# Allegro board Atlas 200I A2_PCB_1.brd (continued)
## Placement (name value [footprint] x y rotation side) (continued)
R361  2.2  [SR0402-TB]  90.31 16.03 270 top
R362  75  [SR0805-TB]  3.35 23.7 270 top
R363  75  [SR0805-TB]  7.39 21.28 270 top
R364  2.2  [SR0402-TB]  87 16.03 270 top
R365  200  [SR0402-TA]  33.96 26.67 0 top
R366  200  [SR0402-TA]  33.96 22.61 0 top
R367  200  [SR0402-TA]  33.96 25.65 0 top
R368  200  [SR0402-TA]  33.96 23.62 0 top
R369  10k*  [SR0402-TA]  105.41 42.32 180 top
R370  0  [SR0402-TA]  108.95 37.19 270 top
R371  47k  [SR0402-TA]  99.26 41.66 90 top
R372  2.2  [SR0805-TB]  115.24 21.7 180 top
R373  2.2  [SR0805-TB]  115.24 19.99 180 top
R374  10k  [SR0402-TA]  108.46 41.55 270 top
R375  0*  [SR0402-TA]  109.09 38.68 0 top
R376  10k*  [SR0402-TA]  106.74 37.19 90 top
R377  10k  [SR0402-TA]  97.23 41.66 270 top
R378  15k  [SR0402-TA]  98.3 39.21 0 top
R379  0  [SR0402-TA]  97.03 39.59 270 top
R380  33  [SR0402-TA]  108.46 39.92 90 top
R381  33  [SR0402-TA]  102.18 29.01 90 top
R382  3m  [SR2512B-TF]  108.58 21.39 180 top
R383  2.2*  [SR0402-TB]  113.49 24.08 0 top
R384  33  [SR0402-TA]  80.03 19.43 270 top
R385  10k  [SR0402-TA]  81.07 21.26 270 top
R386  4.7k  [SR0402-TA]  82.88 21.26 270 top
R387  10k  [SR0402-TA]  84.75 19.43 90 top
R388  47k  [SR0402-TA]  86.62 19.43 270 top
R389  2.2  [SR0805-TB]  84.76 29.34 270 top
R390  47K  [SR0402-TA]  82.35 27.21 180 top
R391  33  [SR0402-TA]  78.23 21.21 270 top
R392  5.1k  [SR0402-TA]  77.22 21.21 90 top
R393  27k  [SR0402-TA]  76.51 23.14 270 top
R394  47k  [SR0402-TA]  74.58 23.14 90 top
R395  475  [SR0402-TA]  77.83 18.61 180 top
R396  0  [SR0402-TA]  89.24 38.74 270 top
R397  2.2  [SR0402-TB]  87.91 16.03 270 top
R398  1k*  [SR0402-TA]  91.15 37.29 90 top
R399  2.49k  [SR0402-TA]  87.47 38.74 90 top
R400  1k*  [SR0402-TA]  53.49 63.25 180 top
R401  2k  [SR0402-TA]  88.55 32.38 0 top
R402  2k  [SR0402-TA]  86.62 38.74 90 top
R403  200  [SR0402-TA]  82.02 19.43 270 top
R404  2k  [SR0402-TA]  81.98 21.26 90 top
R405  1k*  [SR0402-TA]  53.49 67.26 180 top
R406  475  [SR0402-TA]  75.72 19.63 180 top
R407  1k  [SR0402-TA]  77.83 19.63 0 top
R408  100*  [SR0402-TA]  94.92 26.16 90 top
R409  100*  [SR0402-TA]  67.05 26.26 180 top
R410  330  [SR0402-TA]  73.43 42.85 270 top
R411  330  [SR0402-TA]  80.67 43.74 270 top
R412  1k  [SR0402-TA]  75.08 41.71 270 top
R413  1k  [SR0402-TA]  68.58 41.66 270 top
R414  1k  [SR0402-TA]  68.58 39.88 270 top
R415  1k  [SR0402-TA]  75.59 43.1 0 top
R416  0  [SR0402-TA]  24.82 79.78 90 top
R417  330  [SR0402-TA]  100.71 17.42 270 top
R418  330  [SR0402-TA]  87.91 42.85 270 top
R419  330  [SR0402-TA]  95.15 42.72 270 top
R420  1k  [SR0402-TA]  89.69 40.69 270 top
R421  1k  [SR0402-TA]  82.32 40.69 90 top
R422  1k  [SR0402-TA]  82.83 42.09 0 top
R423  1k  [SR0402-TA]  90.07 42.09 0 top
R424  0  [SR0402-TA]  25.83 79.78 90 top
R425  33  [SR0402-TA]  8 73.03 180 top
R426  33  [SR0402-TA]  2.41 75.91 90 top
R427  33  [SR0402-TA]  3.43 75.91 90 top
R428  33  [SR0402-TA]  8 72.01 180 top
R429  0  [SR0402-TA]  88.04 80.26 180 top
R430  0*  [SR0402-TA]  87.22 80.26 0 top
R431  0  [SR0402-TA]  88.04 78.92 180 top
R432  0*  [SR0402-TA]  87.22 78.92 0 top
R433  33  [SR0402-TA]  124.09 70.1 0 top
R434  0  [SR0402-TA]  95.06 71.25 270 top
R435  33  [SR0402-TA]  124.09 76.38 0 top
R436  33  [SR0402-TA]  124.09 87.17 0 top
R437  33  [SR0402-TA]  124.09 83.05 0 top
R438  33  [SR0402-TA]  124.09 81.99 0 top
R439  33  [SR0402-TA]  124.09 79.94 0 top
R440  33  [SR0402-TA]  124.09 80.96 0 top
R441  0*  [SR0402-TA]  95.06 70.43 90 top
R442  33  [SR0402-TA]  124.09 90.04 0 top
R443  33  [SR0402-TA]  123.89 101.6 0 top
R444  33  [SR0402-TA]  124.09 69.12 180 top
R445  33  [SR0402-TA]  124.09 70.95 180 top
R446  0  [SR0402-TA]  96.39 71.25 270 top
R447  33  [SR0402-TA]  123.99 74.52 180 top
R448  33  [SR0402-TA]  124.09 78.96 180 top
R449  33  [SR0402-TA]  124.09 84.08 180 top
R450  33  [SR0402-TA]  124.09 86.14 180 top
R451  0*  [SR0402-TA]  96.39 70.43 90 top
R452  33  [SR0402-TA]  123.89 104.65 180 top
R453  33  [SR0402-TA]  123.89 102.62 180 top
R454  33  [SR0402-TA]  124.09 71.81 0 top
R455  33  [SR0402-TA]  123.89 105.66 0 top
R456  33  [SR0402-TA]  123.89 106.68 0 top
R457  1k  [SR0402-TA]  21.7 73.11 180 top
R458  33  [SR0402-TA]  105.66 84.07 180 top
R459  6.2k  [SR0402-TA]  90.04 74.04 90 top
R460  10k  [SR0402-TA]  88.16 70.76 90 top
R461  200  [SR0402-TA]  127.47 32.38 0 top
R462  10k  [SR0402-TA]  129.92 32.44 180 top
R463  200  [SR0402-TA]  129.92 21.26 0 top
R464  10k  [SR0402-TA]  127.47 21.26 180 top
R465  200  [SR0402-TA]  127.47 26.85 0 top
R466  10k  [SR0402-TA]  129.92 26.85 180 top
R467  10k  [SR0402-TA]  88.52 74.3 0 top
R468  0*  [SR0402-TA]  92.46 87.6 270 top
R469  33  [SR0402-TA]  132.84 43.05 0 top
R470  33  [SR0402-TA]  130.94 43.05 0 top
R471  33  [SR0402-TA]  129.16 43.05 0 top
R472  33  [SR0402-TA]  127.25 43.05 0 top
R473  0  [SR0402-TA]  92.46 86.79 90 top
R474  0*  [SR0402-TA]  91.12 87.6 270 top
R475  0  [SR0402-TA]  91.12 86.79 90 top
R476  0  [SR0402-TA]  88.04 77.84 180 top
R477  0*  [SR0402-TA]  87.22 77.84 0 top
R478  10k  [SR0402-TA]  104.6 45.39 0 top
R479  10k  [SR0402-TA]  105.94 43.84 90 top
R480  10k  [SR0402-TA]  104.6 44.37 0 top
R481  33  [SR0402-TA]  113.14 103.38 180 top
R482  33  [SR0402-TA]  113.14 102.36 180 top
R483  4.7k*  [SR0402-TA]  121.44 102.36 180 top
R484  4.7k*  [SR0402-TA]  121.44 103.38 180 top
R485  4.7k*  [SR0402-TA]  121.44 101.35 180 top
R486  4.7k  [SR0402-TA]  119.28 102.36 0 top
R487  4.7k  [SR0402-TA]  119.28 101.35 0 top
R488  4.7k  [SR0402-TA]  119.28 103.38 0 top
R489  4.7k  [SR0402-TA]  99.06 116.33 180 top
R490  33  [SR0402-TA]  87.76 116.85 0 top
R491  33  [SR0402-TA]  87.76 115.96 0 top
R492  33  [SR0402-TA]  96.81 116.35 0 top
R493  33  [SR0402-TA]  96.81 117.36 0 top
R494  4.7k  [SR0402-TA]  99.09 118.38 0 top
R495  4.7k  [SR0402-TA]  99.09 117.36 0 top
R496  4.7k  [SR0402-TA]  87.76 117.71 180 top
R497  4.7k  [SR0402-TA]  87.76 115.09 180 top
R498  33  [SR0402-TA]  117.55 100.56 0 top
R499  33  [SR0402-TA]  115.72 100.56 180 top
R500  4.7k*  [SR0402-TA]  124.03 100.3 0 top
R501  4.7k  [SR0402-TA]  124.03 99.29 0 top
R502  4.7k*  [SR0402-TA]  124.03 98.27 0 top
R503  4.7k*  [SR0402-TA]  124.03 97.26 0 top
R504  4.7k*  [SR0402-TA]  124.03 96.24 0 top
R505  4.7k  [SR0402-TA]  124.03 95.22 0 top
R506  4.7k*  [SR0402-TA]  124.03 94.21 0 top
R507  4.7k  [SR0402-TA]  124.03 93.19 0 top
R508  4.7k*  [SR0402-TA]  108.86 101.22 180 top
R509  4.7k*  [SR0402-TA]  108.86 100.2 180 top
R510  4.7k*  [SR0402-TA]  108.86 99.19 180 top
R511  4.7k  [SR0402-TA]  108.86 98.17 180 top
R512  4.7k*  [SR0402-TA]  108.86 97.16 180 top
R513  4.7k*  [SR0402-TA]  108.86 96.14 180 top
R514  4.7k*  [SR0402-TA]  108.86 95.12 180 top
R515  4.7k*  [SR0402-TA]  108.86 94.11 180 top
R516  1k  [SR0402-TA]  121.94 100.3 180 top
R517  1k*  [SR0402-TA]  121.94 99.29 180 top
R518  1k  [SR0402-TA]  121.94 98.27 180 top
R519  1k  [SR0402-TA]  121.94 97.26 180 top
R520  1k  [SR0402-TA]  121.94 96.24 180 top
R521  1k*  [SR0402-TA]  121.94 95.22 180 top
R522  1k  [SR0402-TA]  121.94 94.21 180 top
R523  1k*  [SR0402-TA]  121.94 93.19 180 top
R524  1k  [SR0402-TA]  110.95 101.22 0 top
R525  1k  [SR0402-TA]  110.95 100.2 0 top
R526  1k  [SR0402-TA]  110.95 99.19 0 top
R527  1k*  [SR0402-TA]  110.95 98.17 0 top
R528  1k  [SR0402-TA]  110.95 97.16 0 top
R529  1k  [SR0402-TA]  110.95 96.14 0 top
R530  1k  [SR0402-TA]  110.95 95.12 0 top
R531  1k  [SR0402-TA]  110.95 94.11 0 top
R532  4.7k*  [SR0402-TA]  108.86 93.09 180 top
R533  4.7k*  [SR0402-TA]  124.03 91.16 0 top
R534  4.7k*  [SR0402-TA]  124.03 92.18 0 top
R535  1k  [SR0402-TA]  121.94 92.18 180 top
R536  1k  [SR0402-TA]  121.94 91.16 180 top
R537  1k  [SR0402-TA]  110.95 93.09 0 top
R538  0  [SR0402-TA]  88.04 76.51 180 top
R539  0*  [SR0402-TA]  87.22 76.51 0 top
R540  0  [SR0402-TA]  90.1 71.25 270 top
R541  0*  [SR0402-TA]  90.1 70.43 90 top
R542  0  [SR0402-TA]  91.44 71.25 270 top
R543  0*  [SR0402-TA]  91.44 70.43 90 top
R544  0  [SR0402-TA]  86.45 70.76 270 top
R545  0*  [SR0402-TA]  86.86 69.22 180 top
R546  10k  [SR0402-TA]  87.31 70.76 90 top
R547  4.7k*  [SR0402-TA]  73.53 92.71 270 top
R548  1k  [SR0402-TA]  75.31 91.19 180 top
R549  0  [SR0402-TA]  75.51 96.37 0 top
R550  33  [SR0402-TA]  102.23 85.28 180 top
R551  4.7k*  [SR0402-TA]  105.66 85.09 180 top
R552  4.7k  [SR0402-TA]  124.09 88.03 0 top
R553  4.7k  [SR0402-TA]  121.55 79.22 180 top
R554  1k  [SR0402-TA]  107.44 85.09 180 top
R555  0  [SR0402-TA]  105.66 88.65 180 top
R556  33  [SR0402-TA]  122.13 80.92 90 top
R557  33  [SR0402-TA]  119.91 80.92 90 top
R558  0  [SR0402-TA]  65.43 91.9 90 top
R559  0  [SR0402-TA]  66.45 91.9 90 top
R560  1M*  [SR0402-TA]  65.94 93.29 0 top
R561  33*  [SR0402-TA]  16.76 117.35 180 top
R562  33*  [SR0402-TA]  28.45 117.22 180 top
R563  33*  [SR0402-TA]  28.45 116.2 0 top
R564  4.7k  [SR0402-TA]  71.21 76.28 90 top
R565  4.7k  [SR0402-TA]  97.58 60.44 0 top
R566  4.7k  [SR0402-TA]  110.26 76.32 0 top
R567  33*  [SR0402-TA]  16.76 118.36 0 top
R568  4.7k  [SR0402-TA]  72.92 72.03 270 top
R569  4.7k  [SR0402-TA]  70.35 72.03 90 top
R570  6.04k*  [SR0402-TA]  83.47 92.2 270 top
R571  4.7k  [SR0402-TA]  97.58 61.5 0 top
R572  33  [SR0402-TA]  121.02 80.92 90 top
R573  4.7k*  [SR0402-TA]  91.03 104.9 270 top
R574  0*  [SR0402-TA]  82.61 92.2 90 top
R575  33  [SR0402-TA]  120.81 57.71 90 top
R576  10k*  [SR0402-TA]  80.52 105.79 180 top
R577  1M*  [SR0402-TA]  80.52 104.78 180 top
R578  1M*  [SR0402-TA]  81.28 91.9 180 top
R579  0*  [SR0402-TA]  80.9 93.17 270 top
R580  0*  [SR0402-TA]  81.75 93.17 270 top
R581  0*  [SR0402-TA]  100.19 87.68 90 top
R582  0*  [SR0402-TA]  98.86 87.68 90 top
R583  0*  [SR0402-TA]  102.55 87.68 90 top
R584  0*  [SR0402-TA]  101.21 87.68 90 top
R585  0*  [SR0402-TA]  100.19 88.49 270 top
R586  0*  [SR0402-TA]  98.86 88.49 270 top
R587  0*  [SR0402-TA]  102.55 88.49 270 top
R588  0*  [SR0402-TA]  101.21 88.49 270 top
R589  4.7k  [SR0402-TA]  124.15 64.66 0 top
R590  0  [SR0402-TA]  102.23 83.96 0 top
R591  4.7k  [SR0402-TA]  115.98 67.55 180 top
R592  0  [SR0402-TA]  102.23 82.63 0 top
R593  0*  [SR0402-TA]  103.05 83.96 180 top
R594  4.7k  [SR0402-TA]  87.68 114.13 0 top
R595  33  [SR0402-TA]  96.77 114.05 180 top
R596  33  [SR0402-TA]  96.77 115.06 180 top
R597  0*  [SR0402-TA]  103.05 82.63 180 top
R598  4.7k*  [SR0402-TA]  88.52 104.9 90 top
R599  4.7k  [SR0402-TA]  87.68 112.42 180 top
R600  4.7k  [SR0402-TA]  87.68 113.27 180 top
R601  4.7k  [SR0402-TA]  99.06 114.05 180 top
R602  4.7k  [SR0402-TA]  99.06 115.06 180 top
R603  4.7k  [SR0402-TA]  111.19 115.32 180 top
R604  33  [SR0402-TA]  102.75 116.97 0 top
R605  33  [SR0402-TA]  102.75 115.95 0 top
R606  0*  [SR0402-TA]  93.78 105.92 90 top
R607  10k*  [SR0402-TA]  28.45 118.24 180 top
R608  4.7k  [SR0402-TA]  111.19 117.35 0 top
R609  4.7k  [SR0402-TA]  111.19 116.33 0 top
R610  4.7k  [SR0402-TA]  100.72 116.97 0 top
R611  4.7k  [SR0402-TA]  100.72 115.95 0 top
R612  33  [SR0402-TA]  114.2 69.25 90 top
R613  33  [SR0402-TA]  74.89 84.83 180 top
R614  33  [SR0402-TA]  74.89 78.44 180 top
R615  33  [SR0402-TA]  74.89 77.33 180 top
R616  33  [SR0402-TA]  74.89 83.98 180 top
R617  33  [SR0402-TA]  74.89 83.12 180 top
R618  33  [SR0402-TA]  74.9 79.49 180 top
R619  10k*  [SR0402-TA]  16.76 116.33 0 top
R620  33  [SR0402-TA]  114.21 80.92 90 top
R621  33  [SR0402-TA]  87.22 86.42 180 top
R622  33  [SR0402-TA]  70.35 76.28 270 top
R623  33  [SR0402-TA]  73.77 72.03 90 top
R624  33  [SR0402-TA]  71.21 72.03 270 top
R625  33  [SR0402-TA]  97.58 62.51 180 top
R626  33  [SR0402-TA]  110.11 77.33 180 top
R627  33  [SR0402-TA]  70 80.45 0 top
R628  4.7k  [SR0402-TA]  74.89 80.63 180 top
R629  4.7k  [SR0402-TA]  115.85 79.22 180 top
R630  10k*  [SR0402-TA]  30.61 116.2 0 top
R631  1k*  [SR0402-TA]  30.61 115.19 0 top
R632  0  [SR0402-TA]  91.14 106.65 270 top
R633  1k*  [SR0402-TA]  89.79 104.9 0 top
R634  33  [SR0402-TA]  113.1 80.92 90 top
R635  33  [SR0402-TA]  118.95 57.71 90 top
R636  33  [SR0402-TA]  113.22 57.66 90 top
R637  33  [SR0402-TA]  121.74 57.71 90 top
R638  33  [SR0402-TA]  116.55 57.66 90 top
R639  10k*  [SR0402-TA]  89.79 106.93 0 top
R640  0  [SR0402-TA]  19.94 111.3 180 top
R641  33  [SR0402-TA]  116.42 80.92 90 top
R642  0*  [SR0402-TA]  30.61 118.24 180 top
R643  10k  [SR0402-TA]  81.79 70.36 90 top
R644  0  [SR0402-TA]  80.77 70.36 270 top
R645  0*  [SR0402-TA]  79.76 70.36 270 top
R646  4.7k*  [SR0402-TA]  94.56 101.35 0 top
R647  10k  [SR0402-TA]  47.8 30.07 270 top
R648  10k  [SR0402-TA]  58.93 15.52 270 top
R649  10k  [SR0402-TA]  100.86 79.73 90 top
R650  0  [SR0402-TA]  111.58 112.99 270 top
R651  4.7k*  [SR0402-TA]  88.98 103.64 0 top
R652  4.7k*  [SR0402-TA]  82.82 100.46 270 top
R669  33  [SR0402-TA]  115.44 57.66 90 top
R670  33  [SR0402-TA]  115.31 80.92 90 top
R671  33  [SR0402-TA]  113.09 69.25 90 top
R674  33  [SR0402-TA]  114.33 57.66 90 top
R676  33  [SR0402-TA]  120.11 69.25 90 top
R678  33  [SR0402-TA]  119.25 69.25 90 top
R703  4.7k  [SR0402-TA]  93.09 45.01 90 top
R704  4.7k  [SR0402-TA]  94.11 45.01 90 top
RT1  RT  [SF1913]  68.63 29.49 0 top
RT2  RT  [SF1913]  75.95 4.83 270 top
S1  NONE  [TSW5-TG-A]  129.92 30.02 0 top
S2  NONE  [TSW5-TG-A]  129.92 24.43 0 top
S3  NONE  [TSW5-TG-A]  129.92 18.85 0 top
SW1  NONE  [SDSW8-L-B]  129.04 49.5 180 top
T1  NONE  [SL4-0101F]  110.82 11.71 180 top
T2  NONE  [SL4-0101F]  107.69 11.71 180 top
T3  NONE  [SL4-0101F]  106.29 11.71 180 top
T4  NONE  [SL4-0101F]  109.1 11.71 180 top
T5  -99.999999H*  [SL4-0102]  51.05 25.96 90 top
T6  -99.999999H*  [SL4-0102]  41.38 26.25 180 top
T7  -99.999999H*  [SL4-0102]  36.68 26.25 180 top
T8  -99.999999H*  [SL4-0102]  51.05 23.93 90 top
T9  -99.999999H*  [SL4-0102]  43.84 26.25 180 top
T10  -99.999999H*  [SL4-0102]  38.99 26.25 180 top
T19  NONE  [STFM24-40-280]  8.5 32.45 180 top
T20  NONE  [STFM24-40-280]  24.43 32.45 180 top
T21  -99.999999H  [SL4-0102]  103.3 14.05 180 top
TP8  NONE  [TP2-50-5MIL]  126.17 117.36 90 top
TP9  NONE  [TP2-50-5MIL]  8.79 2.95 270 top
U1  NONE  [MLF48A-040-0606L]  11.75 53.59 0 top
U2  NONE  [MLF48A-040-0606L]  57.91 34.16 0 top
U3  SRV05-4  [SOT23-6A]  20.95 98.3 90 top
U4  SRV05-4  [SOT23-6A]  20.95 103.89 270 top
U5  NONE  [MLF20A-050-0503L]  108.18 14.15 180 top
U6  SRV05-4  [SOT23-6A]  103.29 10.24 90 top
U7  NONE  [SOP8-50-154C]  98.73 26.19 0 top
U8  NONE  [MLF6C-065-0202L]  46.79 32.36 0 top
U9  NONE  [MLF6C-065-0202L]  57.91 17.81 0 top
U10  NONE  [MLF48T-050-0707L]  61.21 115.4 0 top
U11  NONE  [SBAT2-1512]  16 66.8 270 top
U12  NONE  [SOP10-20-118]  102.97 39.78 270 top
U13  NONE  [MLF14A-050-0404L]  83.01 24.46 270 top
U14  NONE  [SOT666-6A]  73.3 18.75 270 top
U15  NONE  [MLF20J-050-0404L]  88.06 35.61 180 top
U16  NONE  [SOT23-5F]  101.02 44.37 90 top
U17  NONE  [MLF8A-050-0203L]  116.23 102.36 90 top
U18  NONE  [SOP8-26-118C]  92.23 117.29 270 top
U19  NONE  [SOP24-26-173A]  116.57 95.66 90 top
U20  NONE  [SOP14-26-173C]  120.38 62.89 0 top
U21  NONE  [SOP14-26-173C]  120.05 74.56 0 top
U22  NONE  [SOP8-26-118C]  92.23 113.56 90 top
U23  NONE  [SOP8-26-118C]  107.02 116.46 270 top
U24  NONE  [SOP14-26-173C]  79.88 78.46 90 top
U25  NONE  [SOP14-26-173C]  79.96 84.38 90 top
U26  NONE  [MLF10P-050-0303L]  113.89 110.45 270 top
U27  *  [BGA153-20-1414-ENIG]  6.31 95.66 90 top
U28  SRV05-4  [SOT23-6A]  61.72 16.94 270 top
U29  SRV05-4  [SOT23-6A]  80.54 15.6 180 top
U30  NONE  [SOT23-8]  126.82 37.34 180 top
U31  SRV05-4  [SOT23-6A]  46.96 24.87 180 top
U32  NONE  [SOP14-26-173C]  114.47 62.89 0 top
U33  NONE  [SOP14-26-173C]  114.35 74.56 0 top
U34  NONE  [SOP14-26-173C]  114.35 86.23 0 top
U35  NONE  [SOP14-26-173C]  120.06 86.23 0 top
U36  NONE  [MLF76L-040-0909L]  95.35 80.22 0 top
U37  *  [SOP8-50-208]  22.62 116.3 90 top
U38  *  [MLF76Q-040-0909L]  88.29 98.17 90 top
VCXO1  100MHz  [HSX4-0503]  79.22 116.41 90 top
X1  25MHz  [HSX4-0302B]  4.57 53.34 270 top
X2  25MHz  [HSX4-0302B]  50.93 32.89 270 top
X3  12MHz  [SX4-0303K]  69.85 92.46 90 top
X4  25MHz*  [HSX4-0302B]  83.82 89.15 180 top

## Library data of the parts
C1-C3 C6 C21 C22 C25 C26 C41 C42 C142 C145 = SC0402: signal model: DEFAULT_CAPACITOR_220000pF_2_1
C4 C5 C7 C8 C23 C24 C27 C28 C30 C31 C254 C255 = SC1206-TF
C9 C10 C14 C15 C17 C18 C34 C37 C49 C50 C52 C53 C72 C75 C88 C113 C115 C118-C120 C127 C129-C134 C136-C141 C143 C144 C146 C147 C152 C157 C158 C161 C162 C164 C168-C173 C176 C185-C188 C193-C196 C214 C238 C243 C260 C262 C276 C277 C283-C287 C290-C292 C294-C296 C298-C301 C303 C304 C308 C310 = SC0402-PB: signal model: DEFAULT_CAPACITOR_100000pF_2_1
C11 C16 C19 C20 C29 C32 C35 C155 C156 C163 C167 C182 C217 C222-C225 C228 C231 C232 C241 C247-C249 C259 C261 C266 C309 C322 = SC0805-TD
C12 C40 C48 C59 C74 C78 C94 C100 C101 C123-C126 C153 C165 C175 C181 C205 C210 C220 C245 C253 C263 C270 C302 C346 C347 C352 C355-C361 C364-C366 C368-C370 = SC0603-TD
C13 C63 C82 C87 C201-C204 C242 C264 C265 C271 C273-C275 C280-C282 = SC0402-PB: signal model: DEFAULT_CAPACITOR_10000pF_2_1
C33 C36 C38 C39 C43 C58 C60 C61 C67 C71 C76 C79 C80 C83 C84 C89 C91-C93 C96-C99 C102-C108 C110-C112 C114 C180 C206-C209 C213 C227 C246 C251 C252 C256 C269 C272 C278 C279 C297 C305 C311 C313 C318 C323-C342 C345 C348-C351 C353 C354 C362 C363 C371-C376 = SC0402-PB
C44 C65 C86 C109 C121 C122 C128 C135 C150 C151 C154 C159 C160 C166 C174 C178 C221 C239 C250 C306 C307 C312 C314 C317 C343 C344 = SC0402-PA
C45 C68 = SC0402: signal model: DEFAULT_CAPACITOR_10.000000pF_2_1
C46 C47 C64 = SC0402-PA: signal model: DEFAULT_CAPACITOR_30.000000pF_2_1
C51 C56 C70 C73 C85 C90 C189-C191 C197-C199 C288 C293 = SC0402-PC: signal model: DEFAULT_CAPACITOR_1e+06pF_2_1
C54 C62 C66 C77 C81 C117 C240 = SC0402-PC
C55 C69 C367 = SC0402-PD
C57 = SC0402-PC: signal model: DEFAULT_CAPACITOR_4.7e+06pF_2_1
C95 = SC0402
C116 C184 = SC0402-PA: signal model: DEFAULT_CAPACITOR_33.000000pF_2_1
C148 C149 = SC0402-PA: signal model: DEFAULT_CAPACITOR_150.000000pF_2_1
C177 = SC0402-PA: signal model: DEFAULT_CAPACITOR_100000pF_2_1
C179 = SC0402-PA: signal model: DEFAULT_CAPACITOR_220.000000pF_2_1
C183 C211 C212 C215 C216 C218 C219 C226 C236 C258 C267 C268 = SC0603-TC
C192 C200 = SC1206E
C229 C230 C233 C235 C257 C321 = SC0402-PA: signal model: DEFAULT_CAPACITOR_1000pF_2_1
C234 = SC0402-PA: signal model: DEFAULT_CAPACITOR_15.000000pF_2_1
C237 = SC0402-PB: signal model: DEFAULT_CAPACITOR_2200pF_2_1
C244 = SC0402-PB: signal model: DEFAULT_CAPACITOR_4700pF_2_1
C289 = SC0402-PB: signal model: DEFAULT_CAPACITOR_33000pF_2_1
D1 D2 D17 D18 D25 Q4 Q5 Q8 Q10 Q12-Q16 = SOT23
D3 = HSD0603-LED
D4 D6 D9 D10 D13 D15 D21 D23 = MLF10B-050-0301L
D5 = HSOD523
D7 D32 = SD1107S
D27 = HSOT363-A
D29-D31 = SD0503A
D33 D34 D40 D43 = SOP8-50-173
D35 = SD1710A
D41 = SD2211
F1 = SF6127
F3 = SF2-0302A
ICT1 ICT2 = HOLE125
ID1-ID3 = ID-BOARD
J1 = CARD75-2207
J2 = CARD75-2206A
J3 = HSDC10-1614B: tolerance: i
J4 = RUSB24-050-1009
J5 = RUSB18-200-1524A
J6 J7 = RUSB19-050-1512
J8 = RWBC0104-98T-A
J9 = RPWC0103-RM-C
J10 = FPC51-24E
J11 = SHEAD0220-100-100T-C
J16 = SDIM02161-20B
J17 = RMJ2-0201SRL
L1 L2 = SL0806A
L3 = SL1008H
L4 = SPL0707N
L5 = SPL0404L
L6 L7 = SPL0302E
LB1-LB17 LB20 = SL0402C
LB18 LB19 = SL0805
LED1 LED3 LED4 = SDA4-0606
M1-M4 = RHOLE189-254
M5-M8 = HOLE138-M3
M9 = HOLE177
M10-M12 = RHOLE168-T244B188
MIC1 = SBEEP3-0302
OSC1 = SX4-0302Q
Q1 Q6 = SOT523-3A
Q2 Q3 = SOT23-3
Q11 = RF8-NXP-PSMN1R0
R1-R4 R8 R9 R12-R15 R17 R18 R20 R24-R28 R32-R42 R48-R54 R56 R57 R60 R61 R64-R67 R79-R100 R102-R105 R113-R115 R117-R127 R138-R155 R157 R164-R167 R169 R170 R172-R181 R192-R217 R222 R223 R229-R233 R235-R244 R246-R254 R257 R258 R262 R263 R268-R271 R273 R274 R276-R280 R284-R298 R302-R309 R315-R318 R320-R322 R329 R330 R341 R342 R347 R348 R351-R357 R369 R371 R374-R378 R384-R388 R390-R396 R398-R409 R412-R415 R420-R423 R429-R432 R434 R441 R446 R451 R457-R460 R462 R464 R466-R468 R473-R480 R483-R489 R494-R497 R500-R555 R558-R560 R564-R566 R568-R571 R573 R574 R576-R594 R597-R603 R606-R611 R619 R628-R633 R639 R640 R642-R652 R703 R704 = SR0402-TA
R5 R16 R22 R23 R43-R47 R55 R58 R59 R62 R63 R68-R78 R106-R112 R158-R163 R171 R218-R221 R224-R228 R323-R328 R425-R428 R433 R435-R440 R442-R445 R447-R450 R452-R456 R469-R472 R481 R482 R490-R493 R556 R557 R561-R563 R567 R572 R575 R595 R596 R604 R605 R612-R618 R620-R627 R634-R638 R641 R669-R671 R674 R676 = SR0402-TA: signal model: DEFAULT_RESISTOR_33.000000OHM_2_1
R6 R7 = SR0402-TA: signal model: DEFAULT_RESISTOR_150.000000OHM_2_1
R10 R11 R29-R31 R260 R261 R264-R267 R416 R424 = SR0402-TA: signal model: SR0402-TA_0
R19 R21 R101 R116 R128 R129 R156 R168 R182 R183 R259 R358 R370 R379 R498 R499 = SR0402-TA: signal model: DEFAULT_RESISTOR_0.001OHM_2_1
R130-R137 R184-R191 = SR0402-TB: signal model: DEFAULT_RESISTOR_2.200000OHM_2_1
R234 R281-R283 R299-R301 R314 R340 R346 R350 = SR0402-TA: signal model: DEFAULT_RESISTOR_100.000000OHM_2_1
R245 R410 R411 R418 R419 = SR0402-TA: signal model: DEFAULT_RESISTOR_330.000000OHM_2_1
R255 R256 R310-R313 R331 R332 R339 R343 R349 R359-R361 R364 R397 = SR0402-TB: signal model: SR0402-TB_2.2
R272 R275 = SR0402-TA: signal model: DEFAULT_RESISTOR_5600OHM_2_1
R319 = SR0402-TA: signal model: DEFAULT_RESISTOR_475.000000OHM_2_1
R333-R338 = SR0402-TA: signal model: DEFAULT_RESISTOR_49.900000OHM_2_1
R344 = SR0402-TA: signal model: DEFAULT_RESISTOR_2700OHM_2_1
R345 = SR0402-TA: signal model: DEFAULT_RESISTOR_4300OHM_2_1
R362 R363 R372 R373 R389 = SR0805-TB
R365-R368 R461 R463 R465 = SR0402-TA: signal model: DEFAULT_RESISTOR_200.000000OHM_2_1
R380 R381 = SR0402-TA: signal model: DEFAULT_RESISTOR_10.000000OHM_2_1
R382 = SR2512B-TF
R383 = SR0402-TB
R417 = SR0402-TA: signal model: DEFAULT_RESISTOR_240.000000OHM_2_1
R678 = SR0402-TA: signal model: DEFAULT_RESISTOR_1000.000000OHM_2_1
RT1 RT2 = SF1913
S1-S3 = TSW5-TG-A
SW1 = SDSW8-L-B
T1-T4 = SL4-0101F: signal model: SL4-0101F_SDMM0806U-2-470TB01
T5-T10 T21 = SL4-0102
T19 T20 = STFM24-40-280
TP8 TP9 = TP2-50-5MIL
U1 U2 = MLF48A-040-0606L
U3 U4 U6 U28 U29 U31 = SOT23-6A
U5 = MLF20A-050-0503L
U7 = SOP8-50-154C
U8 U9 = MLF6C-065-0202L
U10 = MLF48T-050-0707L
U11 = SBAT2-1512
U12 = SOP10-20-118
U13 = MLF14A-050-0404L
U14 = SOT666-6A
U15 = MLF20J-050-0404L
U16 = SOT23-5F
U17 = MLF8A-050-0203L
U18 U22 U23 = SOP8-26-118C
U19 = SOP24-26-173A
U20 U21 U24 U25 U32-U35 = SOP14-26-173C
U26 = MLF10P-050-0303L
U27 = BGA153-20-1414-ENIG
U30 = SOT23-8
U36 = MLF76L-040-0909L
U37 = SOP8-50-208
U38 = MLF76Q-040-0909L
VCXO1 = HSX4-0503
X1 X2 X4 = HSX4-0302B
X3 = SX4-0303K

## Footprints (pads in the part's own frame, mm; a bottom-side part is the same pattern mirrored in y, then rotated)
BGA153-20-1414-ENIG
  round 0.305 smd: A1(-3.25,-3.25) A2(-3.25,-2.75) A3(-3.25,-2.25) A4(-3.25,-1.75) A5(-3.25,-1.25) A6(-3.25,-0.75) A7(-3.25,-0.25) A8(-3.25,0.25) A9(-3.25,0.75) A10(-3.25,1.25) A11(-3.25,1.75) A12(-3.25,2.25) A13(-3.25,2.75) A14(-3.25,3.25) B1(-2.75,-3.25) B2(-2.75,-2.75) B3(-2.75,-2.25) B4(-2.75,-1.75) B5(-2.75,-1.25) B6(-2.75,-0.75) B7(-2.75,-0.25) B8(-2.75,0.25) B9(-2.75,0.75) B10(-2.75,1.25) B11(-2.75,1.75) B12(-2.75,2.25) B13(-2.75,2.75) B14(-2.75,3.25) C1(-2.25,-3.25) C2(-2.25,-2.75) C3(-2.25,-2.25) C4(-2.25,-1.75) C5(-2.25,-1.25) C6(-2.25,-0.75) C7(-2.25,-0.25) C8(-2.25,0.25) C9(-2.25,0.75) C10(-2.25,1.25) C11(-2.25,1.75) C12(-2.25,2.25) C13(-2.25,2.75) C14(-2.25,3.25) D1(-1.75,-3.25) D2(-1.75,-2.75) D3(-1.75,-2.25) D4(-1.75,-1.75) D12(-1.75,2.25) D13(-1.75,2.75) D14(-1.75,3.25) E1(-1.25,-3.25) E2(-1.25,-2.75) E3(-1.25,-2.25) E5(-1.25,-1.25) E6(-1.25,-0.75) E7(-1.25,-0.25) E8(-1.25,0.25) E9(-1.25,0.75) E10(-1.25,1.25) E12(-1.25,2.25) E13(-1.25,2.75) E14(-1.25,3.25) F1(-0.75,-3.25) F2(-0.75,-2.75) F3(-0.75,-2.25) F5(-0.75,-1.25) F10(-0.75,1.25) F12(-0.75,2.25) F13(-0.75,2.75) F14(-0.75,3.25) G1(-0.25,-3.25) G2(-0.25,-2.75) G3(-0.25,-2.25) G5(-0.25,-1.25) G10(-0.25,1.25) G12(-0.25,2.25) G13(-0.25,2.75) G14(-0.25,3.25) H1(0.25,-3.25) H2(0.25,-2.75) H3(0.25,-2.25) H5(0.25,-1.25) H10(0.25,1.25) H12(0.25,2.25) H13(0.25,2.75) H14(0.25,3.25) J1(0.75,-3.25) J2(0.75,-2.75) J3(0.75,-2.25) J5(0.75,-1.25) J10(0.75,1.25) J12(0.75,2.25) J13(0.75,2.75) J14(0.75,3.25) K1(1.25,-3.25) K2(1.25,-2.75) K3(1.25,-2.25) K5(1.25,-1.25) K6(1.25,-0.75) K7(1.25,-0.25) K8(1.25,0.25) K9(1.25,0.75) K10(1.25,1.25) K12(1.25,2.25) K13(1.25,2.75) K14(1.25,3.25) L1(1.75,-3.25) L2(1.75,-2.75) L3(1.75,-2.25) L12(1.75,2.25) L13(1.75,2.75) L14(1.75,3.25) M1(2.25,-3.25) M2(2.25,-2.75) M3(2.25,-2.25) M4(2.25,-1.75) M5(2.25,-1.25) M6(2.25,-0.75) M7(2.25,-0.25) M8(2.25,0.25) M9(2.25,0.75) M10(2.25,1.25) M11(2.25,1.75) M12(2.25,2.25) M13(2.25,2.75) M14(2.25,3.25) N1(2.75,-3.25) N2(2.75,-2.75) N3(2.75,-2.25) N4(2.75,-1.75) N5(2.75,-1.25) N6(2.75,-0.75) N7(2.75,-0.25) N8(2.75,0.25) N9(2.75,0.75) N10(2.75,1.25) N11(2.75,1.75) N12(2.75,2.25) N13(2.75,2.75) N14(2.75,3.25) P1(3.25,-3.25) P2(3.25,-2.75) P3(3.25,-2.25) P4(3.25,-1.75) P5(3.25,-1.25) P6(3.25,-0.75) P7(3.25,-0.25) P8(3.25,0.25) P9(3.25,0.75) P10(3.25,1.25) P11(3.25,1.75) P12(3.25,2.25) P13(3.25,2.75) P14(3.25,3.25)
CARD75-2206A
  round 1.092 hole 1.092 unplated: (-10,-1.675)
  round 1.6 hole 1.6 unplated: (10,-1.675)
  rect 0.254x1.549 smd: 1(-9.25,3.05) 2(-9,-3.4) 3(-8.75,3.05) 4(-8.5,-3.4) 5(-8.25,3.05) 6(-8,-3.4) 7(-7.75,3.05) 8(-7.5,-3.4) 9(-7.25,3.05) 10(-7,-3.4) 11(-6.75,3.05) 12(-6.5,-3.4) 13(-6.25,3.05) 14(-6,-3.4) 15(-5.75,3.05) 16(-5.5,-3.4) 17(-5.25,3.05) 18(-5,-3.4) 19(-4.75,3.05) 20(-4.5,-3.4) 21(-4.25,3.05) 22(-4,-3.4) 23(-3.75,3.05) 32(-1.5,-3.4) 33(-1.25,3.05) 34(-1,-3.4) 35(-0.75,3.05) 36(-0.5,-3.4) 37(-0.25,3.05) 38(0,-3.4) 39(0.25,3.05) 40(0.5,-3.4) 41(0.75,3.05) 42(1,-3.4) 43(1.25,3.05) 44(1.5,-3.4) 45(1.75,3.05) 46(2,-3.4) 47(2.25,3.05) 48(2.5,-3.4) 49(2.75,3.05) 50(3,-3.4) 51(3.25,3.05) 52(3.5,-3.4) 53(3.75,3.05) 54(4,-3.4) 55(4.25,3.05) 56(4.5,-3.4) 57(4.75,3.05) 58(5,-3.4) 59(5.25,3.05) 60(5.5,-3.4) 61(5.75,3.05) 62(6,-3.4) 63(6.25,3.05) 64(6.5,-3.4) 65(6.75,3.05) 66(7,-3.4) 67(7.25,3.05) 68(7.5,-3.4) 69(7.75,3.05) 70(8,-3.4) 71(8.25,3.05) 72(8.5,-3.4) 73(8.75,3.05) 74(9,-3.4) 75(9.25,3.05)
  round 0 smd: 24(-3.5,-3.4) 25(-3.25,3.05) 26(-3,-3.4) 27(-2.75,3.05) 28(-2.5,-3.4) 29(-2.25,3.05) 30(-2.001,-3.4) 31(-1.751,3.05)
  rect 1.219x2.743 smd: 76(-10.35,2.825) 77(10.35,2.825)
CARD75-2207
  round 1.092 hole 1.092 unplated: (-10,-1.5)
  round 1.6 hole 1.6 unplated: (10,-1.5)
  rect 0.254x1.422 smd: 1(-9.25,3.149) 2(-9,-3.149) 3(-8.75,3.149) 4(-8.5,-3.149) 5(-8.25,3.149) 6(-8,-3.149) 7(-7.75,3.149) 8(-7.5,-3.149) 9(-7.25,3.149) 10(-7,-3.149) 11(-6.75,3.149) 12(-6.5,-3.149) 13(-6.25,3.149) 14(-6,-3.149) 15(-5.75,3.149) 16(-5.5,-3.149) 17(-5.25,3.149) 18(-5,-3.149) 19(-4.75,3.149) 20(-4.5,-3.149) 21(-4.25,3.149) 22(-4,-3.149) 23(-3.75,3.149) 24(-3.5,-3.149) 25(-3.25,3.149) 26(-3,-3.149) 27(-2.75,3.149) 28(-2.5,-3.149) 29(-2.25,3.149) 30(-2,-3.149) 31(-1.75,3.149) 32(-1.5,-3.149) 33(-1.25,3.149) 34(-1,-3.149) 35(-0.75,3.149) 36(-0.5,-3.149) 37(-0.25,3.149) 38(0,-3.149) 39(0.25,3.149) 40(0.5,-3.149) 41(0.75,3.149) 42(1,-3.149) 43(1.25,3.149) 44(1.5,-3.149) 45(1.75,3.149) 46(2,-3.149) 47(2.25,3.149) 48(2.5,-3.149) 49(2.75,3.149) 50(3,-3.149) 51(3.25,3.149) 52(3.5,-3.149) 53(3.75,3.149) 54(4,-3.149) 55(4.25,3.149) 56(4.5,-3.149) 57(4.75,3.149) 58(5,-3.149) 67(7.25,3.149) 68(7.5,-3.149) 69(7.75,3.149) 70(8,-3.149) 71(8.25,3.149) 72(8.5,-3.149) 73(8.75,3.149) 74(9,-3.149) 75(9.25,3.149)
  round 0 smd: 59(5.25,3.149) 60(5.5,-3.149) 61(5.75,3.149) 62(6,-3.149) 63(6.25,3.149) 64(6.5,-3.149) 65(6.75,3.149) 66(7,-3.149)
  rect 1.219x2.743 smd: 76(-10.35,3) 77(10.35,3)
FPC51-24E
  rect 0.305x0.813 smd: 1(7.5,-1.325) 3(6.9,-1.325) 5(6.3,-1.325) 7(5.7,-1.325) 9(5.1,-1.325) 11(4.5,-1.325) 13(3.9,-1.325) 15(3.3,-1.325) 17(2.7,-1.325) 19(2.1,-1.325) 21(1.5,-1.325) 23(0.9,-1.325) 25(0.3,-1.325) 27(-0.3,-1.325) 29(-0.9,-1.325) 31(-1.5,-1.325) 33(-2.1,-1.325) 35(-2.7,-1.325) 37(-3.3,-1.325) 39(-3.9,-1.325) 41(-4.5,-1.325) 43(-5.1,-1.325) 45(-5.7,-1.325) 47(-6.3,-1.325) 49(-6.9,-1.325) 51(-7.5,-1.325)
  rect 0.305x0.66 smd: 2(7.2,1.55) 4(6.6,1.55) 6(6,1.55) 8(5.4,1.55) 10(4.8,1.55) 12(4.2,1.55) 14(3.6,1.55) 16(3,1.55) 18(2.4,1.55) 20(1.8,1.55) 22(1.2,1.55) 24(0.6,1.55) 26(0,1.55) 28(-0.6,1.55) 30(-1.2,1.55) 32(-1.8,1.55) 34(-2.4,1.55) 36(-3,1.55) 38(-3.6,1.55) 40(-4.2,1.55) 42(-4.8,1.55) 44(-5.4,1.55) 46(-6,1.55) 48(-6.6,1.55) 50(-7.2,1.55)
  rect 0.406x0.965 smd: 52(8.2,-1.05) 53(-8.2,-1.05)
HOLE125
  round 3.175 hole 3.175 unplated: (0,0)
HOLE138-M3
  round 8.001 hole 3.505: 1(0,0)
HOLE177
  round 4.496 hole 4.496 unplated: (0,0)
HSD0603-LED
  rect 0.762x0.813 smd: 1(-0.737,0) 2(0.737,0)
HSDC10-1614B
  rect 0.711x1.219 smd: 1(2.775,7.975) 2(1.675,7.975) 3(0.575,7.975) 4(-0.525,7.975) 5(-1.625,7.975) 6(-2.725,7.975) 7(-3.825,7.975) 8(-4.925,7.975) 9(-5.891,7.975)
  rect 1.016x1.219 smd: 10(4.325,7.975) 11(-6.825,3.675)
  rect 1.016x0.813 smd: 12(-6.825,-2.526)
  rect 1.016x2.794 smd: 13(-6.825,-6.675)
  rect 1.778x1.905 smd: 14(6.675,-7.125)
HSOD523
  rect 0.356x0.559 smd: 1(0.762,0) 2(-0.762,0)
HSOT363-A
  rect 0.356x0.711 smd: 1(-0.65,-0.81) 2(0,-0.81) 3(0.65,-0.81) 4(0.65,0.81) 5(0,0.81) 6(-0.65,0.81)
HSX4-0302B
  rect 1.067x0.965 smd: 1(-0.927,-0.727) 2(0.927,-0.727) 3(0.927,0.727) 4(-0.927,0.727)
HSX4-0503
  rect 1.524x2.235 smd: 1(-1.27,-1.608) 2(1.27,-1.608) 3(1.27,1.608) 4(-1.27,1.608)
ID-BOARD
  round 1.016 smd: 1(0,0)
MLF6C-065-0202L
  rect 0.305x0.406 smd: 1(-0.65,-0.953) 2(0,-0.953) 3(0.65,-0.953) 4(0.65,0.953) 5(0,0.953) 6(-0.65,0.953)
  rect 1.651x0.889 smd: 7(0,0)
MLF8A-050-0203L
  rect 0.254x0.559 smd: 1(-0.75,-1.389) 2(-0.25,-1.389) 3(0.25,-1.389) 4(0.75,-1.389) 5(0.75,1.389) 6(0.25,1.389) 7(-0.25,1.389) 8(-0.75,1.389)
  rect 1.524x1.27 smd: 9(0,0)
MLF10B-050-0301L
  rect 0.254x0.533 smd: 1(-1,-0.417) 2(-0.5,-0.417) 4(0.5,-0.417) 5(1,-0.417) 6(1,0.417) 7(0.5,0.417) 9(-0.5,0.417) 10(-1,0.417)
  rect 0.432x0.686 smd: 3(0,-0.417) 8(0,0.417)
MLF10P-050-0303L
  rect 0.254x0.61 smd: 1(-1,-1.398) 2(-0.5,-1.398) 3(0,-1.398) 4(0.5,-1.398) 5(1,-1.398) 6(1,1.398) 7(0.5,1.398) 8(0,1.398) 9(-0.5,1.398) 10(-1,1.398)
  rect 2.489x1.524 smd: 11(0,0)
MLF14A-050-0404L
  rect 0.559x0.254 smd: 1(-1.629,-0.75) 7(1.629,-0.75) 8(1.629,0.75) 14(-1.629,0.75)
  rect 0.254x0.559 smd: 2(-1,-1.629) 3(-0.5,-1.629) 4(0,-1.629) 5(0.5,-1.629) 6(1,-1.629) 9(1,1.629) 10(0.5,1.629) 11(0,1.629) 12(-0.5,1.629) 13(-1,1.629)
  custom 0.508x0.508 smd: 15(0,0)
MLF20A-050-0503L
  rect 0.61x0.254 smd: 1(-2.155,-0.25) 10(2.155,-0.25) 11(2.155,0.25) 20(-2.155,0.25)
  rect 0.254x0.61 smd: 2(-1.75,-1.155) 3(-1.25,-1.155) 4(-0.75,-1.155) 5(-0.25,-1.155) 6(0.25,-1.155) 7(0.75,-1.155) 8(1.25,-1.155) 9(1.75,-1.155) 12(1.75,1.155) 13(1.25,1.155) 14(0.75,1.155) 15(0.25,1.155) 16(-0.25,1.155) 17(-0.75,1.155) 18(-1.25,1.155) 19(-1.75,1.155)
  rect 2.997x1.016 smd: 21(0,0)
MLF20J-050-0404L
  rect 0.254x0.61 smd: 1(-1,-1.652) 2(-0.5,-1.652) 3(0,-1.652) 4(0.5,-1.652) 5(1,-1.652) 11(1,1.652) 12(0.5,1.652) 13(0,1.652) 14(-0.5,1.652) 15(-1,1.652)
  rect 0.61x0.254 smd: 6(1.652,-1) 7(1.652,-0.5) 8(1.652,0) 9(1.652,0.5) 10(1.652,1) 16(-1.652,1) 17(-1.652,0.5) 18(-1.652,0) 19(-1.652,-0.5) 20(-1.652,-1)
  rect 2.032x2.032 smd: 21(0,0)
MLF48A-040-0606L
  rect 0.203x0.61 smd: 1(-2.2,-2.879) 2(-1.8,-2.879) 3(-1.4,-2.879) 4(-1,-2.879) 5(-0.6,-2.879) 6(-0.2,-2.879) 7(0.2,-2.879) 8(0.6,-2.879) 9(1,-2.879) 10(1.4,-2.879) 11(1.8,-2.879) 12(2.2,-2.879) 25(2.2,2.879) 26(1.8,2.879) 27(1.4,2.879) 28(1,2.879) 29(0.6,2.879) 30(0.2,2.879) 31(-0.2,2.879) 32(-0.6,2.879) 33(-1,2.879) 34(-1.4,2.879) 35(-1.8,2.879) 36(-2.2,2.879)
  rect 0.61x0.203 smd: 13(2.879,-2.2) 14(2.879,-1.8) 15(2.879,-1.4) 16(2.879,-1) 17(2.879,-0.6) 18(2.879,-0.2) 19(2.879,0.2) 20(2.879,0.6) 21(2.879,1) 22(2.879,1.4) 23(2.879,1.8) 24(2.879,2.2) 37(-2.879,2.2) 38(-2.879,1.8) 39(-2.879,1.4) 40(-2.879,1) 41(-2.879,0.6) 42(-2.879,0.2) 43(-2.879,-0.2) 44(-2.879,-0.6) 45(-2.879,-1) 46(-2.879,-1.4) 47(-2.879,-1.8) 48(-2.879,-2.2)
  rect 4.445x4.445 smd: 49(0,0)
MLF48T-050-0707L
  rect 0.254x0.61 smd: 1(-2.75,-3.405) 2(-2.25,-3.405) 3(-1.75,-3.405) 4(-1.25,-3.405) 5(-0.75,-3.405) 6(-0.25,-3.405) 7(0.25,-3.405) 8(0.75,-3.405) 9(1.25,-3.405) 10(1.75,-3.405) 11(2.25,-3.405) 12(2.75,-3.405) 25(2.75,3.405) 26(2.25,3.405) 27(1.75,3.405) 28(1.25,3.405) 29(0.75,3.405) 30(0.25,3.405) 31(-0.25,3.405) 32(-0.75,3.405) 33(-1.25,3.405) 34(-1.75,3.405) 35(-2.25,3.405) 36(-2.75,3.405)
  rect 0.61x0.254 smd: 13(3.405,-2.75) 14(3.405,-2.25) 15(3.405,-1.75) 16(3.405,-1.25) 17(3.405,-0.75) 18(3.405,-0.25) 19(3.405,0.25) 20(3.405,0.75) 21(3.405,1.25) 22(3.405,1.75) 23(3.405,2.25) 24(3.405,2.75) 37(-3.405,2.75) 38(-3.405,2.25) 39(-3.405,1.75) 40(-3.405,1.25) 41(-3.405,0.75) 42(-3.405,0.25) 43(-3.405,-0.25) 44(-3.405,-0.75) 45(-3.405,-1.25) 46(-3.405,-1.75) 47(-3.405,-2.25) 48(-3.405,-2.75)
  rect 5.207x5.207 smd: 49(0,0)
MLF76L-040-0909L
  rect 0.203x0.61 smd: 1(-3.6,-4.405) 2(-3.2,-4.405) 3(-2.8,-4.405) 4(-2.4,-4.405) 5(-2,-4.405) 6(-1.6,-4.405) 7(-1.2,-4.405) 8(-0.8,-4.405) 9(-0.4,-4.405) 10(0,-4.405) 11(0.4,-4.405) 12(0.8,-4.405) 13(1.2,-4.405) 14(1.6,-4.405) 15(2,-4.405) 16(2.4,-4.405) 17(2.8,-4.405) 18(3.2,-4.405) 19(3.6,-4.405) 39(3.6,4.405) 40(3.2,4.405) 41(2.8,4.405) 42(2.4,4.405) 43(2,4.405) 44(1.6,4.405) 45(1.2,4.405) 46(0.8,4.405) 47(0.4,4.405) 48(0,4.405) 49(-0.4,4.405) 50(-0.8,4.405) 51(-1.2,4.405) 52(-1.6,4.405) 53(-2,4.405) 54(-2.4,4.405) 55(-2.8,4.405) 56(-3.2,4.405) 57(-3.6,4.405)
  rect 0.61x0.203 smd: 20(4.405,-3.6) 21(4.405,-3.2) 22(4.405,-2.8) 23(4.405,-2.4) 24(4.405,-2) 25(4.405,-1.6) 26(4.405,-1.2) 27(4.405,-0.8) 28(4.405,-0.4) 29(4.405,0) 30(4.405,0.4) 31(4.405,0.8) 32(4.405,1.2) 33(4.405,1.6) 34(4.405,2) 35(4.405,2.4) 36(4.405,2.8) 37(4.405,3.2) 38(4.405,3.6) 58(-4.405,3.6) 59(-4.405,3.2) 60(-4.405,2.8) 61(-4.405,2.4) 62(-4.405,2) 63(-4.405,1.6) 64(-4.405,1.2) 65(-4.405,0.8) 66(-4.405,0.4) 67(-4.405,0) 68(-4.405,-0.4) 69(-4.405,-0.8) 70(-4.405,-1.2) 71(-4.405,-1.6) 72(-4.405,-2) 73(-4.405,-2.4) 74(-4.405,-2.8) 75(-4.405,-3.2) 76(-4.405,-3.6)
  rect 5.588x5.588 smd: 77(0,0)
MLF76Q-040-0909L
  rect 0.203x0.61 smd: 1(-3.6,-4.379) 2(-3.2,-4.379) 3(-2.8,-4.379) 4(-2.4,-4.379) 5(-2,-4.379) 6(-1.6,-4.379) 7(-1.2,-4.379) 8(-0.8,-4.379) 9(-0.4,-4.379) 10(0,-4.379) 11(0.4,-4.379) 12(0.8,-4.379) 13(1.2,-4.379) 14(1.6,-4.379) 15(2,-4.379) 16(2.4,-4.379) 17(2.8,-4.379) 18(3.2,-4.379) 19(3.6,-4.379) 39(3.6,4.379) 40(3.2,4.379) 41(2.8,4.379) 42(2.4,4.379) 43(2,4.379) 44(1.6,4.379) 45(1.2,4.379) 46(0.8,4.379) 47(0.4,4.379) 48(0,4.379) 49(-0.4,4.379) 50(-0.8,4.379) 51(-1.2,4.379) 52(-1.6,4.379) 53(-2,4.379) 54(-2.4,4.379) 55(-2.8,4.379) 56(-3.2,4.379) 57(-3.6,4.379)
  rect 0.61x0.203 smd: 20(4.379,-3.6) 21(4.379,-3.2) 22(4.379,-2.8) 23(4.379,-2.4) 24(4.379,-2) 25(4.379,-1.6) 26(4.379,-1.2) 27(4.379,-0.8) 28(4.379,-0.4) 29(4.379,0) 30(4.379,0.4) 31(4.379,0.8) 32(4.379,1.2) 33(4.379,1.6) 34(4.379,2) 35(4.379,2.4) 36(4.379,2.8) 37(4.379,3.2) 38(4.379,3.6) 58(-4.379,3.6) 59(-4.379,3.2) 60(-4.379,2.8) 61(-4.379,2.4) 62(-4.379,2) 63(-4.379,1.6) 64(-4.379,1.2) 65(-4.379,0.8) 66(-4.379,0.4) 67(-4.379,0) 68(-4.379,-0.4) 69(-4.379,-0.8) 70(-4.379,-1.2) 71(-4.379,-1.6) 72(-4.379,-2) 73(-4.379,-2.4) 74(-4.379,-2.8) 75(-4.379,-3.2) 76(-4.379,-3.6)
  rect 6.35x6.35 smd: 77(0,0)
RF8-NXP-PSMN1R0
  rect 0.762x1.143 smd: 1(-1.905,-2.725) 2(-0.635,-2.725) 3(0.635,-2.725) 4(1.905,-2.725)
  rect 4.191x2.692 smd: 5(0,0.25)
  rect 0.457x0.965 smd: 6(1.778,2.75) 8(-1.778,2.75)
  rect 4.699x1.524 smd: 7(0,2.75)
RHOLE168-T244B188
  round 6.198 hole 4.267: 1(0,0)
RHOLE189-254
  round 6.604 hole 4.801: 1(0,0)
RMJ2-0201SRL
  round 3.251 hole 3.251 unplated: (-6.35,-8.615) (6.35,-8.615)
  round 1.168 hole 0.762: 1(-4.445,-0.365) 2(-3.175,2.175) 3(-1.905,-0.365) 4(-0.635,2.175) 5(0.635,-0.365) 6(1.905,2.175) 7(3.175,-0.365) 8(4.445,2.175) 9(4.445,8.405) 10(3.175,5.865) 11(1.905,8.405) 12(0.635,5.865) 13(-0.635,8.405) 14(-1.905,5.865) 15(-3.175,8.405) 16(-4.445,5.865)
  round 1.321 hole 0.914: 17(6.86,-4.425) 18(4.32,-4.425) 19(-4.32,-4.425) 20(-6.86,-4.425) 21(6.86,12.335) 22(4.32,12.335) 23(-4.32,12.335) 24(-6.86,12.335)
  oval 1.219x2.235 hole 0.711x1.727: 25(-8.13,-1.505) 26(-8.13,6.875) 27(8.13,-1.505) 28(8.13,6.875)
RPWC0103-RM-C
  round 1.346 hole 1.346 unplated: (-3,-2.3) (3,-2.3)
  rect 3.708x1.321 hole 3.2x0.813: 1(0,6.75)
  oval 1.219x2.921 hole 0.711x2.413: 2(4.8,3.65)
  oval 3.302x1.168 hole 2.794x0.66: 3(0,0.75)
RUSB18-200-1524A
  round 1.118 hole 0.711: 1(-3.5,9.08) 2(-1,9.08) 3(1,9.08) 4(3.5,9.08) 5(4,10.58) 6(2,10.58) 7(0,10.58) 8(-2,10.58) 9(-4,10.58) 10(-3.5,5.88) 11(-1,5.88) 12(1,5.88) 13(3.5,5.88) 14(4,7.38) 15(2,7.38) 16(0,7.38) 17(-2,7.38) 18(-4,7.38)
  oval 1.118x2.921 hole 0.61x2.413: 19(-6.4,6.45) 20(6.4,6.45)
  oval 1.118x2.134 hole 0.61x1.626: 21(-7.8,-1.05) 22(7.8,-1.05)
RUSB19-050-1512
  rect 0.254x2.591 smd: 1(4.5,5.22) 2(4,5.22) 3(3.5,5.22) 4(3,5.22) 5(2.5,5.22) 6(2,5.22) 7(1.5,5.22) 8(1,5.22) 9(0.5,5.22) 10(0,5.22) 11(-0.5,5.22) 12(-1,5.22) 13(-1.5,5.22) 14(-2,5.22) 15(-2.5,5.22) 16(-3,5.22) 17(-3.5,5.22) 18(-4,5.22) 19(-4.5,5.22)
  oval 1.422x3.099 hole 0.813x2.489: 20(-7.25,4.46) 21(7.25,4.46)
  oval 1.422x2.286 hole 0.813x1.702: 22(-7.25,-1.5) 23(7.25,-1.5)
RUSB24-050-1009
  round 0.66 hole 0.66 unplated: (-3.775,2.325) (3.775,2.325)
  rect 0.254x0.813 smd: 1(-2.75,4.305) 2(-2.25,4.305) 3(-1.75,4.305) 4(-1.25,4.305) 5(-0.75,4.305) 6(-0.25,4.305) 7(0.25,4.305) 8(0.75,4.305) 9(1.25,4.305) 10(1.75,4.305) 11(2.25,4.305) 12(2.75,4.305)
  custom 0.225x0.225 hole 0.66: 13(3.55,3.335) 24(-3.55,3.335)
  round 0.66 hole 0.406: 14(2.95,2.325) 15(2.05,2.325) 16(1.7,3.225) 17(0.85,2.325) 18(0.45,3.225) 19(-0.45,3.225) 20(-0.85,2.325) 21(-1.7,3.225) 22(-2.05,2.325) 23(-2.95,2.325)
  oval 1.219x2.413 hole 0.61x1.803: 25(-4.67,3.565) 26(4.67,3.565) 27(-6.02,-0.835) 28(6.02,-0.835)
RWBC0104-98T-A
  round 1.524 hole 1.118: 1(3.75,-0.8) 2(1.25,-0.8) 3(-1.25,-0.8) 4(-3.75,-0.8)
SBAT2-1512
  rect 3.556x2.489 smd: 1(-7.975,0)
  rect 2.972x2.489 smd: 2(8.255,0)
SBEEP3-0302
  round 0.508 hole 0.508 unplated: (0.5,0)
  rect 0.533x0.635 smd: 1(-0.977,0.475) 2(-0.977,-0.475)
  custom 0.362x0.362 smd: 3(-0.001,0)
SC0402
  rect 0.508x0.508 smd: 1(-0.406,0) 2(0.406,0)
SC0402-PA
  rect 0.508x0.508 smd: 1(-0.406,0) 2(0.406,0)
SC0402-PB
  rect 0.508x0.508 smd: 1(-0.406,0) 2(0.406,0)
SC0402-PC
  rect 0.508x0.508 smd: 1(-0.406,0) 2(0.406,0)
SC0402-PD
  rect 0.508x0.508 smd: 1(-0.406,0) 2(0.406,0)
SC0603-TC
  rect 0.762x0.813 smd: 1(-0.699,0) 2(0.699,0)
SC0603-TD
  rect 0.762x0.813 smd: 1(-0.699,0) 2(0.699,0)
SC0805-TD
  rect 0.991x1.27 smd: 1(-0.813,0) 2(0.813,0)
SC1206-TF
  rect 1.295x1.651 smd: 1(-1.346,0) 2(1.346,0)
SC1206E
  rect 1.295x1.905 smd: 1(-1.346,0) 2(1.346,0)
SD0503A
  rect 0.406x0.559 smd: 1(0.753,0) 2(-0.753,0)
SD1107S
  rect 0.864x1.118 smd: 1(1.626,0) 2(-1.626,0)
SD1710A
  rect 1.727x1.676 smd: 1(-1.93,0) 2(1.93,0)
SD2211
  rect 2.184x1.626 smd: 1(2.14,0) 2(-2.14,0)
SDA4-0606
  rect 1.118x0.61 smd: 1(-0.95,-0.45) 2(-0.95,0.45) 3(0.95,0.45) 4(0.95,-0.45)
SDIM02161-20B
  round 1.143 hole 1.143 unplated: (-41,0.25)
  round 1.6 hole 1.6 unplated: (41,0.25)
  rect 0.305x1.778 smd: 1(-30,-3.861) 3(-29.5,-3.861) 5(-29,-3.861) 7(-28.5,-3.861) 9(-28,-3.861) 11(-27.5,-3.861) 13(-27,-3.861) 15(-26.5,-3.861) 17(-26,-3.861) 19(-25.5,-3.861) 21(-25,-3.861) 23(-24.5,-3.861) 25(-24,-3.861) 27(-23.5,-3.861) 29(-23,-3.861) 31(-22.5,-3.861) 33(-22,-3.861) 35(-21.5,-3.861) 37(-21,-3.861) 39(-20.5,-3.861) 41(-20,-3.861) 43(-19.5,-3.861) 45(-19,-3.861) 47(-18.5,-3.861) 49(-18,-3.861) 51(-17.5,-3.861) 53(-17,-3.861) 55(-16.5,-3.861) 57(-16,-3.861) 59(-15.5,-3.861) 61(-15,-3.861) 63(-14.5,-3.861) 65(-14,-3.861) 67(-13.5,-3.861) 69(-13,-3.861) 71(-12.5,-3.861) 73(-12,-3.861) 75(-11.5,-3.861) 77(-11,-3.861) 79(-10.5,-3.861) 81(-10,-3.861) 83(-9.5,-3.861) 85(-9,-3.861) 87(-8.5,-3.861) 89(-8,-3.861) 91(-7.5,-3.861) 93(-7,-3.861) 95(-6.5,-3.861) 97(-6,-3.861) 99(-5.5,-3.861) 101(-5,-3.861) 103(-4.5,-3.861) 105(-4,-3.861) 107(-3.5,-3.861) 109(-3,-3.861) 111(-2.5,-3.861) 113(-2,-3.861) 115(-1.5,-3.861) 117(-1,-3.861) 119(-0.5,-3.861) 121(0,-3.861) 123(0.5,-3.861) 125(1,-3.861) 133(3,-3.861) 135(3.5,-3.861) 137(4,-3.861) 139(4.5,-3.861) 141(5,-3.861) 143(5.5,-3.861) 145(6,-3.861) 147(6.5,-3.861) 149(7,-3.861) 151(7.5,-3.861) 153(8,-3.861) 155(8.5,-3.861) 157(9,-3.861) 159(9.5,-3.861) 161(10,-3.861) 163(10.5,-3.861) 165(11,-3.861) 167(11.5,-3.861) 169(12,-3.861) 171(12.5,-3.861) 173(13,-3.861) 175(13.5,-3.861) 177(14,-3.861) 179(14.5,-3.861) 181(15,-3.861) 183(15.5,-3.861) 185(16,-3.861) 187(16.5,-3.861) 189(17,-3.861) 191(17.5,-3.861) 193(18,-3.861) 195(18.5,-3.861) 197(19,-3.861) 199(19.5,-3.861) 201(20,-3.861) 203(20.5,-3.861) 205(21,-3.861) 207(21.5,-3.861) 209(22,-3.861) 211(22.5,-3.861) 213(23,-3.861) 215(23.5,-3.861) 217(24,-3.861) 219(24.5,-3.861) 221(25,-3.861) 223(25.5,-3.861) 225(26,-3.861) 227(26.5,-3.861) 229(27,-3.861) 231(27.5,-3.861) 233(28,-3.861) 235(28.5,-3.861) 237(29,-3.861) 239(29.5,-3.861) 241(30,-3.861) 243(30.5,-3.861) 245(31,-3.861) 247(31.5,-3.861) 249(32,-3.861) 251(32.5,-3.861) 253(33,-3.861) 255(33.5,-3.861) 257(34,-3.861) 259(34.5,-3.861) 261(35,-3.861) 263(35.5,-3.861) 265(36,-3.861) 267(36.5,-3.861) 269(37,-3.861) 271(37.5,-3.861) 273(38,-3.861) 275(38.5,-3.861) 277(39,-3.861) 279(39.5,-3.861) 281(40,-3.861) 283(-40,-3.861) 285(-39.5,-3.861) 287(-39,-3.861) 289(-38.5,-3.861) 291(-38,-3.861) 293(-37.5,-3.861) 295(-37,-3.861) 297(-36.5,-3.861) 299(-36,-3.861) 301(-35.5,-3.861) 303(-35,-3.861) 305(-34.5,-3.861) 307(-34,-3.861) 309(-33.5,-3.861) 311(-33,-3.861) 313(-32.5,-3.861) 315(-32,-3.861) 317(-31.5,-3.861) 319(-31,-3.861) 321(-30.5,-3.861)
  rect 0.305x1.88 smd: 2(-29.75,3.811) 4(-29.25,3.811) 6(-28.75,3.811) 8(-28.25,3.811) 10(-27.75,3.811) 12(-27.25,3.811) 14(-26.75,3.811) 16(-26.25,3.811) 18(-25.75,3.811) 20(-25.25,3.811) 22(-24.75,3.811) 24(-24.25,3.811) 26(-23.75,3.811) 28(-23.25,3.811) 30(-22.75,3.811) 32(-22.25,3.811) 34(-21.75,3.811) 36(-21.25,3.811) 38(-20.75,3.811) 40(-20.25,3.811) 42(-19.75,3.811) 44(-19.25,3.811) 46(-18.75,3.811) 48(-18.25,3.811) 50(-17.75,3.811) 52(-17.25,3.811) 54(-16.75,3.811) 56(-16.25,3.811) 58(-15.75,3.811) 60(-15.25,3.811) 62(-14.75,3.811) 64(-14.25,3.811) 66(-13.75,3.811) 68(-13.25,3.811) 70(-12.75,3.811) 72(-12.25,3.811) 74(-11.75,3.811) 76(-11.25,3.811) 78(-10.75,3.811) 80(-10.25,3.811) 82(-9.75,3.811) 84(-9.25,3.811) 86(-8.75,3.811) 88(-8.25,3.811) 90(-7.75,3.811) 92(-7.25,3.811) 94(-6.75,3.811) 96(-6.25,3.811) 98(-5.75,3.811) 100(-5.25,3.811) 102(-4.75,3.811) 104(-4.25,3.811) 106(-3.75,3.811) 108(-3.25,3.811) 110(-2.75,3.811) 112(-2.25,3.811) 114(-1.75,3.811) 116(-1.25,3.811) 118(-0.75,3.811) 120(-0.25,3.811) 122(0.25,3.811) 124(0.75,3.811) 134(3.25,3.811) 136(3.75,3.811) 138(4.25,3.811) 140(4.75,3.811) 142(5.25,3.811) 144(5.75,3.811) 146(6.25,3.811) 148(6.75,3.811) 150(7.25,3.811) 152(7.75,3.811) 154(8.25,3.811) 156(8.75,3.811) 158(9.25,3.811) 160(9.75,3.811) 162(10.25,3.811) 164(10.75,3.811) 166(11.25,3.811) 168(11.75,3.811) 170(12.25,3.811) 172(12.75,3.811) 174(13.25,3.811) 176(13.75,3.811) 178(14.25,3.811) 180(14.75,3.811) 182(15.25,3.811) 184(15.75,3.811) 186(16.25,3.811) 188(16.75,3.811) 190(17.25,3.811) 192(17.75,3.811) 194(18.25,3.811) 196(18.75,3.811) 198(19.25,3.811) 200(19.75,3.811) 202(20.25,3.811) 204(20.75,3.811) 206(21.25,3.811) 208(21.75,3.811) 210(22.25,3.811) 212(22.75,3.811) 214(23.25,3.811) 216(23.75,3.811) 218(24.25,3.811) 220(24.75,3.811) 222(25.25,3.811) 224(25.75,3.811) 226(26.25,3.811) 228(26.75,3.811) 230(27.25,3.811) 232(27.75,3.811) 234(28.25,3.811) 236(28.75,3.811) 238(29.25,3.811) 240(29.75,3.811) 242(30.25,3.811) 244(30.75,3.811) 246(31.25,3.811) 248(31.75,3.811) 250(32.25,3.811) 252(32.75,3.811) 254(33.25,3.811) 256(33.75,3.811) 258(34.25,3.811) 260(34.75,3.811) 262(35.25,3.811) 264(35.75,3.811) 266(36.25,3.811) 268(36.75,3.811) 270(37.25,3.811) 272(37.75,3.811) 274(38.25,3.811) 276(38.75,3.811) 278(39.25,3.811) 280(39.75,3.811) 282(-39.75,3.811) 284(-39.25,3.811) 286(-38.75,3.811) 288(-38.25,3.811) 290(-37.75,3.811) 292(-37.25,3.811) 294(-36.75,3.811) 296(-36.25,3.811) 298(-35.75,3.811) 300(-35.25,3.811) 302(-34.75,3.811) 304(-34.25,3.811) 306(-33.75,3.811) 308(-33.25,3.811) 310(-32.75,3.811) 312(-32.25,3.811) 314(-31.75,3.811) 316(-31.25,3.811) 318(-30.75,3.811) 320(-30.25,3.811)
  round 0 smd: 126(1.25,3.811) 127(1.5,-4.095) 128(1.75,3.811) 129(2,-4.095) 130(2.25,3.811) 131(2.5,-4.095) 132(2.75,3.811)
  rect 2.997x5.156 smd: 322(-44,1) 323(44,1)
SDSW8-L-B
  rect 1.143x2.286 smd: 1(-3.81,-4.395) 2(-1.27,-4.395) 3(1.27,-4.395) 4(3.81,-4.395) 5(-3.81,4.395) 6(-1.27,4.395) 7(1.27,4.395) 8(3.81,4.395)
SF2-0302A
  rect 1.295x1.803 smd: 1(-1.346,0) 2(1.346,0)
SF1913
  rect 1.27x3.15 smd: 1(-2.362,0) 2(2.362,0)
SF6127
  rect 2.286x3.175 smd: 1(-2.54,0) 2(2.54,0)
SHEAD0220-100-100T-C
  rect 1.27x3.302 smd: 1(-24.13,-2.665) 2(-24.13,2.665) 3(-21.59,-2.665) 4(-21.59,2.665) 5(-19.05,-2.665) 6(-19.05,2.665) 7(-16.51,-2.665) 8(-16.51,2.665) 9(-13.97,-2.665) 10(-13.97,2.665) 11(-11.43,-2.665) 12(-11.43,2.665) 13(-8.89,-2.665) 14(-8.89,2.665) 15(-6.35,-2.665) 16(-6.35,2.665) 17(-3.81,-2.665) 18(-3.81,2.665) 19(-1.27,-2.665) 20(-1.27,2.665) 21(1.27,-2.665) 22(1.27,2.665) 23(3.81,-2.665) 24(3.81,2.665) 25(6.35,-2.665) 26(6.35,2.665) 27(8.89,-2.665) 28(8.89,2.665) 29(11.43,-2.665) 30(11.43,2.665) 31(13.97,-2.665) 32(13.97,2.665) 33(16.51,-2.665) 34(16.51,2.665) 35(19.05,-2.665) 36(19.05,2.665) 37(21.59,-2.665) 38(21.59,2.665) 39(24.13,-2.665) 40(24.13,2.665)
SL4-0101F
  rect 0.254x0.33 smd: 1(-0.25,-0.29) 2(-0.25,0.29) 3(0.25,0.29) 4(0.25,-0.29)
SL4-0102
  rect 0.406x0.889 smd: 1(-0.406,-0.864) 2(-0.406,0.864) 3(0.406,0.864) 4(0.406,-0.864)
SL0402C
  rect 0.483x0.66 smd: 1(-0.4,0) 2(0.4,0)
SL0805
  rect 0.94x1.27 smd: 1(-0.851,0) 2(0.851,0)
SL0806A
  rect 0.762x1.651 smd: 1(-0.821,0) 2(0.821,0)
SL1008H
  rect 1.321x2.032 smd: 1(-1.26,0) 2(1.26,0)
SOP8-26-118C
  rect 0.356x1.651 smd: 1(-0.975,-2.276) 2(-0.325,-2.276) 3(0.325,-2.276) 4(0.975,-2.276) 5(0.975,2.276) 6(0.325,2.276) 7(-0.325,2.276) 8(-0.975,2.276)
SOP8-50-154C
  rect 0.635x1.778 smd: 1(-1.905,-2.667) 2(-0.635,-2.667) 3(0.635,-2.667) 4(1.905,-2.667) 5(1.905,2.667) 6(0.635,2.667) 7(-0.635,2.667) 8(-1.905,2.667)
SOP8-50-173
  rect 0.635x1.778 smd: 1(-1.905,-2.667) 2(-0.635,-2.667) 3(0.635,-2.667) 4(1.905,-2.667) 5(1.905,2.667) 6(0.635,2.667) 7(-0.635,2.667) 8(-1.905,2.667)
SOP8-50-208
  rect 0.635x1.778 smd: 1(-1.905,-3.556) 2(-0.635,-3.556) 3(0.635,-3.556) 4(1.905,-3.556) 5(1.905,3.556) 6(0.635,3.556) 7(-0.635,3.556) 8(-1.905,3.556)
SOP10-20-118
  rect 0.254x1.473 smd: 1(-1,-2.212) 2(-0.5,-2.212) 3(0,-2.212) 4(0.5,-2.212) 5(1,-2.212) 6(1,2.212) 7(0.5,2.212) 8(0,2.212) 9(-0.5,2.212) 10(-1,2.212)
SOP14-26-173C
  rect 0.356x1.727 smd: 1(-1.95,-3.014) 2(-1.3,-3.014) 3(-0.65,-3.014) 4(0,-3.014) 5(0.65,-3.014) 6(1.3,-3.014) 7(1.95,-3.014) 8(1.95,3.014) 9(1.3,3.014) 10(0.65,3.014) 11(0,3.014) 12(-0.65,3.014) 13(-1.3,3.014) 14(-1.95,3.014)
SOP24-26-173A
  rect 0.356x1.676 smd: 1(-3.575,-2.988) 2(-2.925,-2.988) 3(-2.275,-2.988) 4(-1.625,-2.988) 5(-0.975,-2.988) 6(-0.325,-2.988) 7(0.325,-2.988) 8(0.975,-2.988) 9(1.625,-2.988) 10(2.275,-2.988) 11(2.925,-2.988) 12(3.575,-2.988) 13(3.575,2.988) 14(2.925,2.988) 15(2.275,2.988) 16(1.625,2.988) 17(0.975,2.988) 18(0.325,2.988) 19(-0.325,2.988) 20(-0.975,2.988) 21(-1.625,2.988) 22(-2.275,2.988) 23(-2.925,2.988) 24(-3.575,2.988)
SOT23
  rect 1.016x1.27 smd: 1(-1.016,-1.143) 2(1.016,-1.143) 3(0,1.143)
SOT23-3
  rect 0.635x1.016 smd: 1(-0.955,-1.122) 2(0.955,-1.122) 3(0,1.122)
SOT23-5F
  rect 0.457x1.321 smd: 1(-0.94,-1.359) 2(0,-1.359) 3(0.94,-1.359) 4(0.94,1.359) 5(-0.94,1.359)
SOT23-6A
  rect 0.61x1.143 smd: 1(-0.95,-1.225) 2(0,-1.225) 3(0.95,-1.225) 4(0.95,1.225) 5(0,1.225) 6(-0.95,1.225)
SOT23-8
  rect 0.356x1.27 smd: 1(-0.975,-1.35) 2(-0.325,-1.35) 3(0.325,-1.35) 4(0.975,-1.35) 5(0.975,1.35) 6(0.325,1.35) 7(-0.325,1.35) 8(-0.975,1.35)
SOT523-3A
  rect 0.381x1.016 smd: 1(-0.5,-0.864) 2(0.5,-0.864)
  rect 0.508x1.016 smd: 3(0,0.864)
SOT666-6A
  rect 0.254x0.508 smd: 1(-0.5,-0.699) 2(0,-0.699) 3(0.5,-0.699) 4(0.5,0.699) 5(0,0.699) 6(-0.5,0.699)
SPL0302E
  rect 1.27x2.235 smd: 1(-1.035,0) 2(1.035,0)
SPL0404L
  rect 1.448x3.81 smd: 1(-1.775,0) 2(1.775,0)
SPL0707N
  rect 2.489x3.404 smd: 1(-3.094,0) 2(3.094,0)
SR0402-TA
  rect 0.508x0.508 smd: 1(-0.406,0) 2(0.406,0)
SR0402-TB
  rect 0.508x0.508 smd: 1(-0.406,0) 2(0.406,0)
SR0805-TB
  rect 0.838x1.143 smd: 1(-0.927,0) 2(0.927,0)
SR2512B-TF
  rect 2.845x3.175 smd: 1(-2.64,0) 2(2.64,0)
STFM24-40-280
  rect 0.508x2.184 smd: 1(-5.5,-4.56) 2(-4.5,-4.56) 3(-3.5,-4.56) 4(-2.5,-4.56) 5(-1.5,-4.56) 6(-0.5,-4.56) 7(0.5,-4.56) 8(1.5,-4.56) 9(2.5,-4.56) 10(3.5,-4.56) 11(4.5,-4.56) 12(5.5,-4.56) 13(5.5,4.56) 14(4.5,4.56) 15(3.5,4.56) 16(2.5,4.56) 17(1.5,4.56) 18(0.5,4.56) 19(-0.5,4.56) 20(-1.5,4.56) 21(-2.5,4.56) 22(-3.5,4.56) 23(-4.5,4.56) 24(-5.5,4.56)
SX4-0302Q
  rect 1.346x1.245 smd: 1(-1.125,-0.925) 2(1.125,-0.925) 3(1.125,0.925) 4(-1.125,0.925)
SX4-0303K
  rect 1.397x1.346 smd: 1(-1.298,-0.973) 2(1.298,-0.973) 3(1.298,0.973) 4(-1.298,0.973)
TP2-50-5MIL
  round 0.559 hole 0.254: 1(0,0) 2(1.27,0)
TSW5-TG-A
  rect 1.016x0.762 smd: 1(-2.108,0.8) 2(2.108,0.8) 3(-2.108,-0.8) 4(2.108,-0.8)
  rect 1.118x0.813 smd: 5(0,-1.503)
unnamed#2
  round 0.305 smd: A1(-0.5,-0.5) A2(-0.5,0) A3(-0.5,0.5) B1(0,-0.5) B2(0,0) B3(0,0.5) C1(0.5,-0.5) C2(0.5,0) C3(0.5,0.5)

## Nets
3V3_USB30_SW: C113.2 C115.2 D7.1 R241.1 U5.1 U5.6 U5.10
12V_FAN: D32.1 L3.1 R353.2 R356.2 U26.6 U26.7 U26.8 U26.9 U26.10
AGND_AUDIO: C147.2 C148.2 C149.2 J16.302 J16.305
AGND_MIC: D27.1 LB11.1 MIC1.3 R257.1
DVDD_PHY0_RG: C63.2 R115.1 U1.29
DVDD_PHY1_RG: C82.2 R157.1 U2.29
